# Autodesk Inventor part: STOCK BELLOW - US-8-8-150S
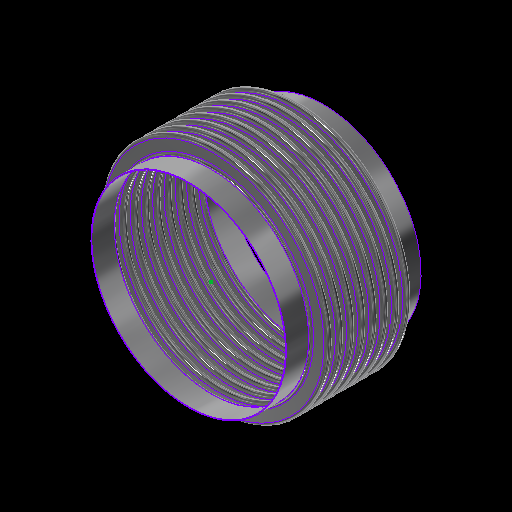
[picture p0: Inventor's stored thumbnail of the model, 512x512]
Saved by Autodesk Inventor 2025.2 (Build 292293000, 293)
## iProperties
Category: 20 GA (0.036 THICK)
RuleStatus: InUse
Created: 2024-01
Part Number: STOCK BELLOW - US-8-8-150S
Project: =STOCK BELLOWS: <Stock Number><SFILL>
Material: ASTM A240-304
Description: =STOCK BELLOWS: <Stock Number>, <SID_> I.D., <SOD_> O.D., <SPLY_> PLY, <Category>, <SNET_CONS> CONS.<PITCH_><STANGENT_> TANGENT<SFILL>
Document SubType Name: Sheet Metal
Designer: GS
Stock Number: U.S-8-8-150S
Surface Area: 5949.24 cm^2
Volume: 270.266 cm^3
Sheet Metal Rule: Default
Appearance: STAINLESS STEEL
Mass: 2177.61 g
Density: 8.05729 g/cm^3
THK: 0.036
ID: 3.500
OD: 4.250
CONS_: 2
PITCH: 0.500
TANGENT: 0.500
BELLOWS_UPSET: 0.000
d79: 1.000
d82: 1.000
d83: 26.000
d84: 24.000
d174: 8
d214: 8
STHK_: 0.036
SID_: 8.625
SOD_: 10.125
SPITCH_: 0.500
STANGENT__: 1.000
SBELLOWS_UPSET_: 0.000
SDIFF_TAN: 1.000
d252: 2
d275: 2
d287: 0.050
d289: 0.500
d290: 0.000
SOD_NECK: 8 11/16
PLY: 1
PSET: 4.178
PBAR: 1.035
COUNTER: 1.500
NET_TUBE: 3.071
CONS: 2
S_CONS: 0
NET_CONS: 2
ID_M: 88.90 mm
OD_M: 107.95 mm
THK_M: 0.91 mm
ID_U: 3.500 in
OD_U: 4.250 in
THK_U: 0.036 in
TANGENT2: 0.500
TAN_TO_TAN: 1.000 in
d80: 2.571
d81: 10
SID: 2.375
SCONS_: 8
SPITCH: 0.250
STANGENT_: 1.000
SBELLOWS_UPSET: 0.000
SNET_CONS: 8
SS_CONS: 0
SCONS: 8
d190: 8
d191: 1
d192: 1
d193: 8
d194: 0
SIZE: 8.00
PRESSURE: 150
d230: 8
STANGENT: 4.000
SPLY_: 1
d233: 8
d234: 0
d263: 2
d265: 1
d268: 2
d269: 0
d286: 2
d288: 1
d291: 2
d292: 0
SREROLL: 0.750
BLETP: 0.000 ul
PRES_Copy: 85
MATTABLE: 20 GA (0.036 THICK)
PART_NUMBER: U.S-8-8-150S
PITCH_: =, <SPITCH_> PITCH,
CFILL: .
SFILL: .
MESH: ,
COMP: 0.81
EXT: 0.41
LAT: 0.11
ANG: 573
ASR: 2401
LSR: 17807
ANSR: 414
PRES: 150
COMPM: 8.1
EXTM: 4.05
LATM: 1.10
ASRM: 420.487
PRESM: 10.342
LSRM: 3118.540
ANSRM: 72.504
TEMPMIN: 20
TEMPMAX: 800
TEMPMINM: -7
TEMPMAXM: 427
WEIGHTM: 2.178
WEIGHT: 4.801
Author: GS
Keywords: 20 GA (0.036 THICK)
Comments: =STOCK BELLOW - <STOCK NUMBER>
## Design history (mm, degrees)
sketch "Sketch2"
  geometry: L1 (0, -177.245)-(0, 562.856) reference; L2 (45.364, 0)-(44.45, 0); L3 (48.082, -2.718)-(50.343, -2.718); L4 (48.082, -3.632)-(50.343, -3.632); L5 (50.343, -9.982)-(48.082, -9.982); L6 (50.343, -9.068)-(48.082, -9.068); L7 (45.364, -12.7)-(44.45, -12.7); L8 (48.082, 0)-(48.082, -12.7); L9 (50.343, -6.35)-(53.975, -6.35); L10 (44.45, 0)-(44.45, -12.7); L11 (20.376, 102.841)-(20.376, 101.926); L12 (58.262, 457.127)-(58.262, 349.177); L13 (58.262, 444.427)-(58.262, 336.477); L14 (93.133, -58.817)-(93.133, -71.517); L15 (118.746, -66.401)-(118.746, -66.401); L16 (50.343, -9.068)-(50.343, -9.982); L17 (48.082, -9.068)-(48.082, -9.982); L18 (48.082, -9.525)-(50.343, -9.525); L19 (53.975, 0)-(53.975, -12.7); L20 (-50.343, -9.068)-(-50.343, -9.982); L21 (-50.343, -2.718)-(-48.082, -2.718); L22 (-50.343, -3.632)-(-48.082, -3.632); L23 (-48.082, -9.068)-(-50.343, -9.068); L24 (-50.343, -9.525)-(-48.082, -9.525); L25 (-48.082, -9.982)-(-50.343, -9.982); L26 (-48.082, -9.068)-(-48.082, -9.982); L27 (-44.45, 0.653)-(-44.45, -12.047); L28 (-48.082, -6.35)-(-44.45, -6.35); L29 (-50.343, 0.653)-(-50.343, -12.7); L30 (-53.061, 0)-(-53.975, 0); L31 (-53.975, 0)-(-53.975, -12.7); L32 (-53.061, -12.7)-(-53.975, -12.7); A1 r 2.718 centre (48.082, 0) between (45.364, 0) and (48.082, -2.718); A2 r 3.632 centre (48.082, 0) between (44.45, 0) and (48.082, -3.632); A3 r 3.632 centre (50.343, -6.35) between (50.343, -9.982) and (50.343, -2.718); A4 r 2.718 centre (50.343, -6.35) between (50.343, -9.068) and (50.343, -3.632); A5 r 2.718 centre (48.082, -12.7) between (48.082, -9.982) and (45.364, -12.7); A6 r 3.632 centre (48.082, -12.7) between (48.082, -9.068) and (44.45, -12.7); A7 r 3.175 centre (50.343, -6.35) between (50.343, -9.525) and (53.518, -6.35); A8 r 3.175 centre (48.082, -12.7) between (48.082, -9.525) and (44.907, -12.7); A9 r 2.718 centre (-50.343, -12.7) between (-50.343, -9.982) and (-53.061, -12.7); A10 r 2.718 centre (-48.082, -6.35) between (-48.082, -9.068) and (-48.082, -3.632); A11 r 3.175 centre (-48.082, -6.35) between (-48.082, -9.525) and (-44.907, -6.35); A12 r 3.632 centre (-48.082, -6.35) between (-48.082, -9.982) and (-48.082, -2.718); A13 r 3.175 centre (-50.343, -12.7) between (-50.343, -9.525) and (-53.518, -12.7); A14 r 3.632 centre (-50.343, -12.7) between (-50.343, -9.068) and (-53.975, -12.7); A15 r 2.718 centre (-50.343, 0) between (-53.061, 0) and (-50.343, -2.718); A16 r 3.632 centre (-50.343, 0) between (-53.975, 0) and (-50.343, -3.632); 10 further points
  constraints: 62 end point, 38 point on circle, 20 tangent, 16 centre point, 12 parallel, 9 midpoint, 7 vertical, 6 coincident, 6 concentric, 6 point on line, 4 equal radius, 4 perpendicular, 3 horizontal, 1 collinear, 1 horizontal alignment, 10 other
  dimensions: "THK" = 0.9144 distance of L11.start L11.end; "ID" = 88.9 distance of L11.end point (20.376, 13.026); "OD" = 107.95 distance of L12.start L12.end; "PITCH" = 12.7 distance of L12.start L13.start; "TANGENT" = 12.7 distance of L14.start L14.end; "BELLOWS_UPSET" = 0 distance of L15.start L15.end; "d43" = 88.9 diameter of L10 L1 (= ID); "d44" = 107.95 diameter of L9.end L1 (= OD); "d45" = 0.9144 distance between parallel lines of L5 L6 (computed from THK, PLY); "d46" = 3.6322 radius of A3 (computed from PITCH, THK, PLY); "UPSET_PITCH" = 12.7 distance of L2.end L7.end (derived); "SIDEWALL_ANGLE" = 360 deg dimension on L3 L9 (derived); "CON_GAP" = 5.4356 distance of point (48.082, -9.068) point (48.082, -3.632) (derived); "TAN1" = 4.98728 dimension on A8 (derived); "TAN2" = 4.98728 dimension on A7 (derived); "LEG1" = 2.2606 distance of L18.start L18.end (derived); "d278" = 0.9144 distance between parallel lines of L25 L23 (derived); "d279" = 3.6322 radius of A12 (derived); "d280" = 12.7 distance of L30.end L31.end (derived); "d281" = 360 deg dimension on L21 L28 (derived); "d282" = 5.4356 distance of point (-50.343, -9.068) point (-50.343, -3.632) (derived); "d283" = 4.98728 dimension on A13 (derived); "d284" = 4.98728 dimension on A11 (derived); "d285" = 2.2606 distance of L24.start L24.end (derived); "d293" = 88.9 diameter of L27 L1 (derived); "d294" = 107.95 diameter of L31 L1 (derived)
  node "Sketch Rectangular Pattern1" dims "d31" = 25.4, "ID" = 88.9
  node "Sketch Rectangular Pattern2" dims "d39" = 25.4, "PITCH" = 12.7
revolve "CONS" stored, may be unused: angle "d48" = 90 deg
node "BELLOW MIDPLANE"
pattern_linear "Rectangular Pattern2" dims "d52" = 12.7 (= UPSET_PITCH)
sketch "Sketch5"
  geometry: C1 r 45.364 at (0, 0) reference; C2 r 44.45 at (0, 0) reference
extrude "TANGENT" new body sketch "Sketch5" distance "d53" = 12.7 (= TANGENT); taper "d54" = 0 deg
revolve "SAMETAN" stored, may be unused: angle "d65" = 90 deg
revolve "DIFFTAN" stored, may be unused: angle "d70" = 90 deg
sketch "Sketch9"
  geometry: L1 (53.319, 0)-(-53.319, 0) reference; L2 (0, -17.78)-(0, 17.78) reference; L3 (38.085, 0)-(-38.085, 0); L4 (38.085, -11.906)-(38.085, 11.906); L5 (25.385, -11.906)-(25.385, 11.906); L6 (13.15, 11.906)-(13.15, -11.906); L7 (-25.385, -11.906)-(-25.385, 11.906); L8 (-38.085, -11.906)-(-38.085, 11.906); L9 (37.291, -11.906)-(37.291, 11.906); L10 (38.085, -11.906)-(37.291, -11.906); L11 (38.085, 11.906)-(37.291, 11.906); L12 (13.546, 11.906)-(12.753, 11.906); L13 (12.753, 11.906)-(12.753, -11.906); L14 (12.753, -11.906)-(13.546, -11.906); L15 (13.546, -11.906)-(13.546, 11.906); L16 (-13.546, 11.906)-(-13.546, -11.906); L17 (-13.15, 11.906)-(-13.15, -11.906); L18 (-13.546, -11.906)-(-12.753, -11.906); L19 (-12.753, -11.906)-(-12.753, 11.906); L20 (-12.753, 11.906)-(-13.546, 11.906); L21 (-38.085, -11.906)-(-37.291, -11.906); L22 (-37.291, -11.906)-(-37.291, 11.906); L23 (-37.291, 11.906)-(-38.085, 11.906); L24 (-38.085, 11.906)-(-38.085, -11.906); L25 (38.085, -0.397)-(-38.085, -0.397); L26 (-38.085, -0.397)-(-38.085, 0.397); L27 (-38.085, 0.397)-(38.085, 0.397); L28 (38.085, 0.397)-(38.085, -0.397); L29 (-38.085, 11.906)-(38.085, 11.906); L30 (38.085, 11.906)-(38.085, 12.7); L31 (38.085, 12.7)-(-38.085, 12.7); L32 (-38.085, 12.7)-(-38.085, 11.906); L33 (38.085, -11.906)-(-38.085, -11.906); L34 (-38.085, -11.906)-(-38.085, -12.7); L35 (-38.085, -12.7)-(38.085, -12.7); L36 (38.085, -12.7)-(38.085, -11.906); 30 further points
  constraints: 68 end point, 13 midpoint, 13 parallel, 8 horizontal, 7 perpendicular, 6 equal length, 3 point on line, 2 vertical, 14 other
  dimensions: "d115" = 23.8125 distance of L4.start L4.end (derived); "d116" = 12.7 distance between parallel lines of L4 L5 (derived); "d117" = 12.23516 distance between parallel lines of L5 L6 (derived); "d125" = 38.53427 distance between parallel lines of L7 L6 (derived); "d127" = 12.7 distance between parallel lines of L8 L7 (derived); "d128" = 24.93516 distance between parallel lines of L6 L4 (derived); "d130" = 76.16943 distance between parallel lines of L8 L4 (derived); "RULER_THK" = 0.79375 distance between parallel lines of L4 L9; "d135" = 0.79375 distance of L13.end L14.end (derived); "d138" = 26.29911 distance of L13.end L16.end (derived); "d143" = 0.79375 distance of L22.end L8.end (derived); "d144" = 0.79375 distance between parallel lines of L27 L25 (derived)
extrude "RULER" join sketch "Sketch9" distance "d149" = 0.79375 (derived); taper "d150" = 0 deg
extrude "BARS" join sketch "Sketch9" distance "d151" = 0.79375 (derived); taper "d152" = 0 deg
pattern_linear "Rectangular Pattern4" dims "d155" = 26.29911 (derived)
sketch "Sketch13"
  geometry: L1 (93.149, -52.467)-(93.149, -77.867); L2 (110.452, 0)-(109.537, 0); L3 (110.452, -12.7)-(109.537, -12.7); L4 (124.955, -9.982)-(113.17, -9.982); L5 (124.955, -9.068)-(113.17, -9.068); L6 (124.955, -6.35)-(128.588, -6.35); L7 (113.17, -2.718)-(124.955, -2.718); L8 (113.17, 0)-(113.17, -12.7); L9 (109.537, 0)-(109.537, -12.7); L10 (58.254, -239.256)-(58.254, -496.431); L11 (58.254, -251.956)-(58.254, -509.131); L12 (58.254, -277.356)-(58.254, -534.531); L13 (58.254, -290.056)-(58.254, -547.231); L14 (58.254, -302.756)-(58.254, -559.931); L15 (58.254, -315.456)-(58.254, -572.631); L16 (58.254, -328.156)-(58.254, -585.331); L17 (58.254, -264.656)-(58.254, -521.831); L18 (20.376, 102.841)-(20.376, 101.926); L19 (113.17, -3.632)-(124.955, -3.632); L20 (0, -722.965)-(0, 240.475) reference; L21 (-25.718, 0)-(154.305, 0) reference; A1 r 2.718 centre (113.17, 0) between (110.452, 0) and (113.17, -2.718); A2 r 2.718 centre (113.17, -12.7) between (113.17, -9.982) and (110.452, -12.7); A3 r 3.632 centre (113.17, -12.7) between (113.17, -9.068) and (109.537, -12.7); A4 r 2.718 centre (124.955, -6.35) between (124.955, -9.068) and (124.955, -3.632); A5 r 3.632 centre (124.955, -6.35) between (124.955, -9.982) and (124.955, -2.718); A6 r 3.632 centre (113.17, 0) between (109.537, 0) and (113.17, -3.632); 6 further points; 1 other entity
  constraints: 38 end point, 15 point on circle, 9 tangent, 6 centre point, 6 parallel, 5 vertical alignment, 4 point on line, 4 vertical, 3 coincident, 3 concentric, 2 collinear, 2 equal radius, 1 horizontal, 1 perpendicular, 23 other
  dimensions: "SBELLOWS_UPSET_" = 0 distance of point (118.762, -66.401) point (118.762, -66.401); "STOTAL_THK_BELLOW__" = 0.9144 distance between parallel lines of L4 L5 (derived); "d224" = 3.6322 radius of A5 (derived); "d225" = 12.7 distance of L2.end L3.end (derived); "SSIDEWALL_ANGLE_" = 360 deg dimension on L7 L6 (derived); "SSCON_GAP_" = 5.4356 distance of point (113.17, -9.068) point (113.17, -3.632) (derived); "d235" = 219.075 diameter of L9 L20 (derived); "d236" = 257.175 diameter of L6.end L20 (derived)
  node "Sketch Rectangular Pattern4" dims "d228" = 25.4
  node "Sketch Rectangular Pattern5" dims "d229" = 25.4
revolve "SBELLOW" stored, may be unused: angle "d197" = 90 deg
pattern_linear "Rectangular Pattern5" dims "d204" = 12.7 (derived)
revolve "STANGENT" stored, may be unused: angle "d240" = 90 deg
revolve "SSAMETAN" stored, may be unused: angle "d241" = 90 deg
revolve "SDIFFTAN" stored, may be unused: angle "d246" = 90 deg
revolve "INVCON" stored, may be unused: angle "d295" = 90 deg
pattern_linear "Rectangular Pattern6" dims "d298" = 12.7 (derived)
revolve "INVTANGENT" stored, may be unused: angle "d302" = 90 deg
revolve "INVSAMETAN" stored, may be unused: angle "d307" = 90 deg
revolve "INVDIFFTAN" stored, may be unused: angle "d312" = 90 deg
sketch "ID BELLOW MOUNT CALC"
  geometry: L1 (44.45, 0)-(38.1, 0); L2 (38.1, 0)-(38.1, 12.7); L3 (38.1, 12.7)-(44.45, 12.7); L4 (44.45, 12.7)-(44.45, 0); L5 (36.513, 12.7)-(35.598, 12.7); L6 (35.598, 12.7)-(35.598, 0); L7 (35.598, 0)-(36.513, 0); L8 (36.513, 0)-(36.513, 12.7); L9 (0, -2.54)-(0, 15.24) reference; L10 (-8.89, 0)-(53.34, 0) reference; 1 further point
  constraints: 16 end point, 5 parallel, 2 collinear, 2 horizontal, 2 perpendicular
  dimensions: "d314" = 12.7 distance of L5.end L6.end (derived); "d315" = 0.9144 distance of L5.start L5.end (derived); "IG" = 1.5875 distance between parallel lines of L2 L8; "PIPE_OD" = 88.9 diameter of L4 L9; "PIPE_WALL" = 6.35 distance of L2.end L3.end; "ID_MT_BELLOW" = 71.1962 diameter of L6 L9 (derived)
revolve "CFILL" stored, may be unused: angle "d320" = 90 deg
pattern_linear "Rectangular Pattern7" dims "d323" = 12.7 (derived)
revolve "SFILL" stored, may be unused: angle "d324" = 90 deg
pattern_linear "Rectangular Pattern8" dims "d327" = 12.7 (derived)
node "STOCK BELLOW MIDPLANE"
node "BELLOW"
sketch "Sketch6"
  geometry: L1 (-12.7, 45.364)-(0, 45.364); L2 (0, 45.364)-(0, 44.45); L3 (0, 44.45)-(-12.7, 44.45); L4 (-12.7, 44.45)-(-12.7, 45.364); L5 (10.16, 0)-(-60.96, 0) reference; L6 (-38.1, -89.422)-(-38.1, 153.44) reference; 1 further point
  constraints: 8 end point, 2 parallel, 1 horizontal, 1 perpendicular
  dimensions: "d61" = 12.7 distance of L2.end L3.end (derived); "d62" = 0.9144 distance of L1.end L2.end (derived); "d63" = 88.9 diameter of L3 L5 (derived); "d64" = 25.4 distance between parallel lines of L4 L6 (derived)
sketch "Sketch12"
  geometry: 1 further point
sketch "Sketch14"
  geometry: L1 (-25.4, 110.452)-(0, 110.452); L2 (0, 110.452)-(0, 109.537); L3 (0, 109.537)-(-25.4, 109.537); L4 (-25.4, 109.537)-(-25.4, 110.452); L5 (5.08, 0)-(-30.48, 0) reference; L6 (0, -22.09)-(0, 132.542) reference; 1 further point
  constraints: 8 end point, 2 parallel, 1 collinear, 1 horizontal, 1 perpendicular
  dimensions: "d237" = 0.9144 distance of L3.end L1.start (derived); "d238" = 219.075 diameter of L3 L5 (derived); "d239" = 25.4 distance of L1.start L1.end (derived); "SOD_NECK" = 220.9038 diameter of L1 L5 (derived)
sketch "Sketch15"
  geometry: L1 (-22.09, 0)-(132.542, 0) reference; L2 (109.538, -101.6)-(110.452, -101.6); L3 (110.452, -101.6)-(110.452, -127); L4 (110.452, -127)-(109.537, -127); L5 (109.537, -127)-(109.538, -101.6); L6 (0, -154.94)-(0, 40.64) reference; 1 further point
  constraints: 8 end point, 2 parallel, 1 horizontal, 1 perpendicular
  dimensions: "d205" = 25.4 distance of L4.end L2.start (derived); "d206" = 0.9144 distance of L3.end L4.end (derived); "d207" = 219.075 diameter of L5 L6 (derived); "d208" = 101.6 distance between parallel lines of L1 L2 (derived)
node "TANGENT_"
node "SAME_TAN"
sketch "Sketch8"
  geometry: L1 (45.364, -25.4)-(44.45, -25.4); L2 (44.45, -25.4)-(44.45, -38.1); L3 (44.45, -38.1)-(45.364, -38.1); L4 (45.364, -38.1)-(45.364, -25.4); L5 (0, -48.26)-(0, 22.86) reference; L6 (-89.422, 0)-(153.44, 0) reference; 1 further point
  constraints: 8 end point, 2 parallel, 1 horizontal, 1 perpendicular
  dimensions: "d66" = 88.9 diameter of L2 L5 (derived); "TOTAL_THK_BELLOW" = 0.9144 distance of L2.end L3.end (derived); "d68" = 25.4 distance between parallel lines of L1 L6 (derived); "d69" = 12.7 distance of L1.end L2.end (derived)
node "DIFF_TAN"
node "Sketch Rectangular Pattern3" dims "d138" = 26.29911 (derived), "d141" = 25.4
node "SBELLOW_"
node "STANGENT_"
node "SSAME_TAN"
sketch "Sketch16"
  geometry: L1 (110.452, -101.6)-(109.538, -101.6); L2 (109.538, -101.6)-(109.538, -127); L3 (109.538, -127)-(110.452, -127); L4 (110.452, -127)-(110.452, -101.6); L5 (0, -154.94)-(0, 40.64) reference; L6 (-22.09, 0)-(132.542, 0) reference; 1 further point
  constraints: 8 end point, 2 parallel, 1 horizontal, 1 perpendicular
  dimensions: "SDIFF_TAN" = 25.4 distance of L3.end L1.start; "d243" = 0.9144 distance of L2.end L3.end (derived); "d244" = 101.6 distance between parallel lines of L1 L6 (derived); "d245" = 219.075 diameter of L2 L5 (derived)
node "SDIFF_TAN"
body "Solid15"
sketch "Sketch17"
  geometry: L1 (53.975, 12.7)-(53.061, 12.7); L2 (53.061, 12.7)-(53.061, 0); L3 (53.061, 0)-(53.975, 0); L4 (53.975, 0)-(53.975, 12.7); L5 (0, -2.54)-(0, 15.24) reference; L6 (-10.795, 0)-(64.77, 0) reference; 2 further points
  constraints: 8 end point, 2 parallel, 1 horizontal, 1 midpoint, 1 perpendicular, 1 point on line
  dimensions: "INVTANGENT" = 12.7 distance of L3.end L1.start (derived); "d300" = 0.9144 distance of L1.start L1.end (derived); "d301" = 107.95 diameter of L4 L5 (derived)
body "Solid16"
sketch "Sketch18"
  geometry: L1 (53.975, -25.4)-(53.061, -25.4); L2 (53.061, -25.4)-(53.061, -38.1); L3 (53.061, -38.1)-(53.975, -38.1); L4 (53.975, -38.1)-(53.975, -25.4); L5 (-10.795, 0)-(64.77, 0) reference; L6 (0, -48.26)-(0, 22.86) reference; 1 further point
  constraints: 8 end point, 2 parallel, 1 horizontal, 1 perpendicular
  dimensions: "d303" = 25.4 distance between parallel lines of L1 L5 (derived); "d304" = 12.7 distance of L3.end L1.start (derived); "d305" = 0.9144 distance of L2.end L3.end (derived); "d306" = 107.95 diameter of L4 L6 (derived)
body "Solid17"
sketch "Sketch19"
  geometry: L1 (53.975, -25.4)-(53.061, -25.4); L2 (53.061, -25.4)-(53.061, -38.1); L3 (53.061, -38.1)-(53.975, -38.1); L4 (53.975, -38.1)-(53.975, -25.4); L5 (0, -48.26)-(0, 22.86) reference; L6 (-10.795, 0)-(64.77, 0) reference; 1 further point
  constraints: 8 end point, 2 parallel, 1 horizontal, 1 perpendicular
  dimensions: "d308" = 12.7 distance of L1.end L2.end (derived); "d309" = 107.95 diameter of L4 L5 (derived); "d310" = 0.9144 distance of L2.end L3.end (derived); "d311" = 25.4 distance between parallel lines of L1 L6 (derived)
body "Solid18"
body "Solid19"
body "Solid20"
other parameters: "BMPL" = -50.8, "PSET" = 106.1212 (computed from OD, THK, PLY) [user parameter], "PBAR" = 26.29911 (= 0.570796 x PITCH + OD - ID) [user parameter; used in 1 equation term], "COUNTER" = 15 [user parameter], "NET_TUBE" = 77.99823 (computed from CONS_, PBAR, TANGENT) [user parameter], "S_CONS" = 0 [user parameter; used in 1 equation term], "ID_M" = 88.9 (= ID) [user parameter], "OD_M" = 107.95 (= OD) [user parameter], "THK_M" = 0.9144 (= THK) [user parameter], "ID_U" = 88.9 (= ID) [user parameter], "OD_U" = 107.95 (= OD) [user parameter], "THK_U" = 0.9144 (= THK) [user parameter], "D_UNITS" = 0 [user parameter], "TANGENT2" = 12.7 [user parameter], "TAN_TO_TAN" = 25.4 [user parameter], "OD_NECK" = 90.7288 [user parameter], "d79" = 25.4, "d80" = 65.29823 [user parameter], "d82" = 25.4, "d83" = 660.4, "d84" = 609.6, "sa_0" = 4, "FRAME_THK" = 0.79375 [user parameter], "CON_FLAT" = 12.23516 [user parameter], "SID" = 60.325 [user parameter], "SPITCH" = 6.35 [user parameter], "STANGENT_" = 25.4 [user parameter], "SBELLOWS_UPSET" = 0 [user parameter], "SS_CONS" = 0 [user parameter], "STAN_TO_TAN_" = 101.6 [user parameter], "d100" = 0.9144 [user parameter], "d191" = 25.4 [user parameter], "d194" = 0 [user parameter], "STANGENT" = 101.6 [user parameter], "d234" = 0 [user parameter], "SUPSET_PITCH_" = 12.7 [user parameter], "d269" = 0 [user parameter], "d287" = 1.27, "d289" = 12.7, "d290" = 0, "d292" = 0 [user parameter], "Thickness" = 3.048 (derived), "KFactor" = 4.4, "BendRadius" = 3.048 (derived), "BendReliefWidth" = 3.048 (derived), "BendReliefDepth" = 1.524 (derived), "CornerReliefSize" = 12.192 (derived), "SeamGap" = 0.00508, "MinimumRemnant" = 6.096 (derived), "TransitionRadius" = 3.048 (derived), "JacobiRadiusSize" = 3.048 (derived), "GapSize" = 3.048 (derived), "SREROLL" = 19.05 [user parameter], "CUR_STK_PITCH" = 12.7 [user parameter], "d328" = -50.8 (derived), "ASR" = 24010 [user parameter], "LSR" = 178070 [user parameter], "BLETP" = 0 [user parameter], "ASRM" = 4204.8713 [user parameter], "PRESM" = 103.41975 [user parameter], "LSRM" = 31185.3991 [user parameter], "ANSRM" = 725.0382 [user parameter], "TEMPMIN" = 2664.83333 [user parameter], "TEMPMAX" = 6998.16667 [user parameter], "TEMPMINM" = 2664.83333 [user parameter], "TEMPMAXM" = 6998.16667 [user parameter], "WEIGHT" = 21.77609 [user parameter], "WEIGHTM" = 0.02178 [user parameter]
